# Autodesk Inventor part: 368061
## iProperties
Created: 2006-06
Part Number: 368061
Document SubType Name: Modeling
Designer: I.Baliuc
Material: 8.8 vz
Description: Sperrzahnmutter
Density: 7.85 g/cm^3
Mass: 15.1747 g
Surface Area: 13.6804 cm^2
Volume: 1.93308 cm^3
Abmessung: M10
Author: T.Messerschmitt
Revision Number: 368061
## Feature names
1. Basis1
